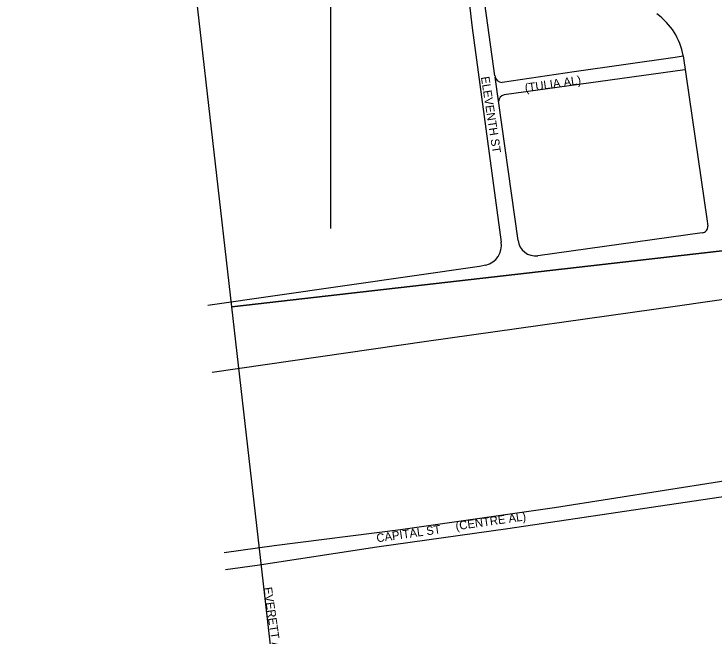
# Model space of a CAD drawing. Extents: x -9648 to 41057, y -12373 to 40276.
# Drawn here: x 7917 to 8744, y -1665 to -930 of the extents above; entities that cross this region are included whole.
import ezdxf

# ---------------------------------------------------------------- set-up
doc = ezdxf.new("R2010")
doc.units = 0
doc.layers.add('SC_Scratch1', color=7, linetype='Continuous')
doc.layers.add('SH_Data', color=7, linetype='Continuous')

msp = doc.modelspace()

# ---------------------------------------------------------------- linework, layer by layer
at = {"layer": 'SC_Scratch1'}
for p, q in [((8174.5, -1275.41), (7917.3, 969.91)), ((8174.5, -1275.41), (7917.3, 969.91)), ((8291.42, -1182.84), (8291.42, -750.3)), ((8174.5, -1275.41), (9704.49, -1100.16)), ((9704.49, -1100.16), (8174.5, -1275.41)), ((9704.49, -1100.16), (8174.5, -1275.41)), ((8431.69, -3520.73), (8174.5, -1275.41))]:
    msp.add_line(p, q, dxfattribs=at)
at = {"layer": 'SH_Data'}
for p, q in [((8709.5, -995.36), (8496.09, -1025.03)), ((8512.53, -1196.99), (8485.6, -1004.14)), ((8730.01, -1187.74), (8535.71, -1215.19)), ((8467.14, -1227.73), (8146.1, -1273.67)), ((8474.58, -1225.95), (8467.14, -1227.73))]:
    msp.add_line(p, q, dxfattribs=at)
for points in [[(8485.2, -1002.4), (8458.2, -808.7), (8432.09, -617.31), (8414.33, -479.7), (8387.3, -286.14), (8593.49, -256.82)], [(8095.82, -523.26), (8102.52, -523.01), (8117.9, -521.3), (8143.5, -517.54), (8396.73, -483.98), (8399.01, -492.88), (8442.84, -814.27), (8458.49, -945.87), (8492.74, -1198.77)], [(8707.49, -979.16), (8697.9, -980.96), (8578.7, -998.03), (8493.71, -1010.28)], [(8707.69, -978.76), (8735.6, -1171.54), (8736.61, -1179.94)], [(8970.44, -1235.61), (8700.66, -1274.36), (8404.28, -1316.33), (8151.39, -1352.66)], [(9056.06, -1629.76), (9045.23, -1577.57), (9013.95, -1441.58), (8946.96, -1450.82), (8894.76, -1458.85), (8750.58, -1481.93), (8555.59, -1512.44), (8373.61, -1538.34), (8224.42, -1557.43), (8165.66, -1565.77)], [(8166.98, -1585.3), (8204.63, -1580.04), (8345.62, -1558.56), (8500.61, -1536.87), (8980.17, -1465.8)]]:
    msp.add_lwpolyline(points, dxfattribs=at)
for centre, radius, start, end in [((8630.93, -992.99), 78.08, 10.50718, 54.31818), ((8493.76, -1001.66), 8.62, 184.28518, 269.66318), ((8498.16, -1033.49), 8.7, 103.74518, 175.47018), ((8729.46, -1180.59), 7.18, 274.43918, 5.15218), ((8533.48, -1194.17), 21.14, 187.64518, 276.05918), ((8468.57, -1202.28), 24.42, 284.25018, 8.26818)]:
    msp.add_arc(centre, radius, start, end, dxfattribs=at)

# ---------------------------------------------------------------- texts
at = {"layer": 'SC_Scratch1'}
for s, rotation, p in [('ELEVENTH ST', 278.80418, (8468.64, -1004.06)), ('(TULIA AL)', 8.27318, (8521.31, -1021.77)), ('(CENTRE AL)', 8.08118, (8439.42, -1539.04)), ('CAPITAL ST', 8.08118, (8345.99, -1553.29)), ('EVERETT AL', 278.39218, (8211.94, -1606.84))]:
    msp.add_text(s, height=10, rotation=rotation, dxfattribs=at).set_placement(p)

doc.saveas('drawing.dxf')
